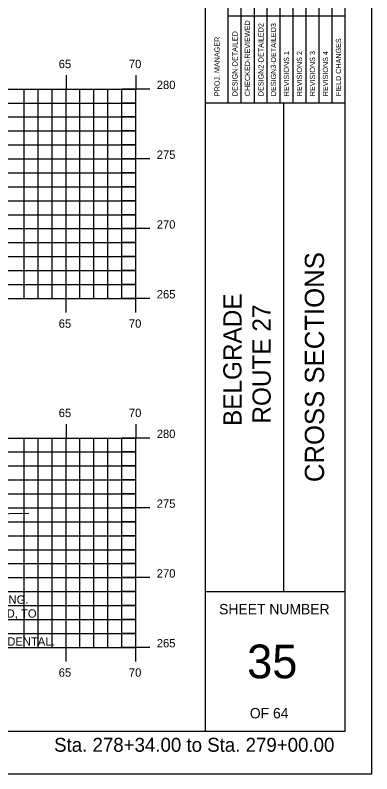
# Model space of a CAD drawing. Extents: x 854676 to 854846, y 366268 to 366378.
# Drawn here: x 854820.5 to 854846, y 366268.2 to 366322.5 of the extents above; entities that cross this region are included whole.
import ezdxf

# ---------------------------------------------------------------- set-up
doc = ezdxf.new("R2010")
doc.units = 0
for name, color, linetype in [('ANNOTATION', 7, 'Continuous'), ('BORDER', 7, 'Continuous'), ('H_V ANNOTATION', 7, 'Continuous'), ('HIGHWAY_TITLE', 7, 'Continuous'), ('MAJOR', 7, 'Continuous'), ('MINOR', 7, 'Continuous'), ('PLOT BOUNDARY', 7, 'Continuous'), ('S_Roadway_Centerline', 7, 'Continuous')]:
    doc.layers.add(name, color=color, linetype=linetype)

msp = doc.modelspace()

# ---------------------------------------------------------------- linework, layer by layer
at = {"layer": 'BORDER'}
for p, q in [((854834.107, 366271.236), (854834.107, 366376.239)), ((854844.107, 366271.236), (854844.107, 366376.236)), ((854834.107, 366316.239), (854844.107, 366316.239)), ((854839.698, 366281.239), (854839.698, 366316.239)), ((854834.107, 366281.239), (854844.107, 366281.239)), ((854684.107, 366271.236), (854844.107, 366271.236))]:
    msp.add_line(p, q, dxfattribs=at)
for points in [[(854836.654, 366316.242), (854836.654, 366333.739)], [(854837.586, 366333.739), (854837.586, 366316.242)], [(854838.517, 366316.242), (854838.517, 366333.739)], [(854839.449, 366316.242), (854839.449, 366333.739)], [(854840.381, 366316.242), (854840.381, 366333.739)], [(854841.312, 366316.242), (854841.312, 366333.739)], [(854842.244, 366316.242), (854842.244, 366333.739)], [(854843.176, 366316.242), (854843.176, 366333.739)], [(854835.722, 366316.242), (854835.722, 366333.033)], [(854835.721, 366322.489), (854844.107, 366322.489)]]:
    msp.add_lwpolyline(points, dxfattribs=at)
at = {"layer": 'MAJOR'}
for p, q in [((854824.106, 366318.238), (854824.106, 366317.236)), ((854829.106, 366318.238), (854829.106, 366317.236)), ((854689.106, 366317.236), (854829.106, 366317.236)), ((854689.106, 366317.236), (854829.106, 366317.236)), ((854824.106, 366302.236), (854824.106, 366317.236)), ((854830.108, 366317.236), (854828.104, 366317.236)), ((854829.106, 366302.236), (854829.106, 366317.236)), ((854829.106, 366302.236), (854829.106, 366317.236)), ((854689.106, 366312.236), (854829.106, 366312.236)), ((854830.108, 366312.236), (854828.104, 366312.236)), ((854689.106, 366307.236), (854829.106, 366307.236)), ((854830.108, 366307.236), (854828.104, 366307.236)), ((854689.106, 366302.236), (854829.106, 366302.236)), ((854689.106, 366302.236), (854829.106, 366302.236)), ((854824.106, 366301.234), (854824.106, 366302.236)), ((854830.108, 366302.236), (854828.104, 366302.236)), ((854829.106, 366301.234), (854829.106, 366302.236)), ((854824.106, 366293.238), (854824.106, 366292.236)), ((854829.106, 366293.238), (854829.106, 366292.236)), ((854689.106, 366292.236), (854829.106, 366292.236)), ((854689.106, 366292.236), (854829.106, 366292.236)), ((854824.106, 366277.236), (854824.106, 366292.236)), ((854830.108, 366292.236), (854828.104, 366292.236)), ((854829.106, 366277.236), (854829.106, 366292.236)), ((854829.106, 366277.236), (854829.106, 366292.236)), ((854689.106, 366287.236), (854829.106, 366287.236)), ((854830.108, 366287.236), (854828.104, 366287.236)), ((854689.106, 366282.236), (854829.106, 366282.236)), ((854830.108, 366282.236), (854828.104, 366282.236)), ((854689.106, 366277.236), (854829.106, 366277.236)), ((854689.106, 366277.236), (854829.106, 366277.236)), ((854824.106, 366276.234), (854824.106, 366277.236)), ((854830.108, 366277.236), (854828.104, 366277.236)), ((854829.106, 366276.234), (854829.106, 366277.236))]:
    msp.add_line(p, q, dxfattribs=at)
at = {"layer": 'MINOR'}
for p, q in [((854821.106, 366302.236), (854821.106, 366317.236)), ((854822.106, 366302.236), (854822.106, 366317.236)), ((854823.106, 366302.236), (854823.106, 366317.236)), ((854825.106, 366302.236), (854825.106, 366317.236)), ((854826.106, 366302.236), (854826.106, 366317.236)), ((854827.106, 366302.236), (854827.106, 366317.236)), ((854828.106, 366302.236), (854828.106, 366317.236)), ((854689.106, 366316.236), (854829.106, 366316.236)), ((854829.106, 366316.236), (854828.104, 366316.236)), ((854689.106, 366315.236), (854829.106, 366315.236)), ((854829.106, 366315.236), (854828.104, 366315.236)), ((854689.106, 366314.236), (854829.106, 366314.236)), ((854829.106, 366314.236), (854828.104, 366314.236)), ((854689.106, 366313.236), (854829.106, 366313.236)), ((854829.106, 366313.236), (854828.104, 366313.236)), ((854689.106, 366311.236), (854829.106, 366311.236)), ((854829.106, 366311.236), (854828.104, 366311.236)), ((854689.106, 366310.236), (854829.106, 366310.236)), ((854829.106, 366310.236), (854828.104, 366310.236)), ((854689.106, 366309.236), (854829.106, 366309.236)), ((854829.106, 366309.236), (854828.104, 366309.236)), ((854689.106, 366308.236), (854829.106, 366308.236)), ((854829.106, 366308.236), (854828.104, 366308.236)), ((854689.106, 366306.236), (854829.106, 366306.236)), ((854829.106, 366306.236), (854828.104, 366306.236)), ((854689.106, 366305.236), (854829.106, 366305.236)), ((854829.106, 366305.236), (854828.104, 366305.236)), ((854689.106, 366304.236), (854829.106, 366304.236)), ((854829.106, 366304.236), (854828.104, 366304.236)), ((854689.106, 366303.236), (854829.106, 366303.236)), ((854829.106, 366303.236), (854828.104, 366303.236)), ((854821.106, 366277.236), (854821.106, 366292.236)), ((854822.106, 366277.236), (854822.106, 366292.236)), ((854823.106, 366277.236), (854823.106, 366292.236)), ((854825.106, 366277.236), (854825.106, 366292.236)), ((854826.106, 366277.236), (854826.106, 366292.236)), ((854827.106, 366277.236), (854827.106, 366292.236)), ((854828.106, 366277.236), (854828.106, 366292.236)), ((854689.106, 366291.236), (854829.106, 366291.236)), ((854829.106, 366291.236), (854828.104, 366291.236)), ((854689.106, 366290.236), (854829.106, 366290.236)), ((854829.106, 366290.236), (854828.104, 366290.236)), ((854689.106, 366289.236), (854829.106, 366289.236)), ((854829.106, 366289.236), (854828.104, 366289.236)), ((854689.106, 366288.236), (854829.106, 366288.236)), ((854829.106, 366288.236), (854828.104, 366288.236)), ((854689.106, 366286.236), (854829.106, 366286.236)), ((854829.106, 366286.236), (854828.104, 366286.236)), ((854689.106, 366285.236), (854829.106, 366285.236)), ((854829.106, 366285.236), (854828.104, 366285.236)), ((854689.106, 366284.236), (854829.106, 366284.236)), ((854829.106, 366284.236), (854828.104, 366284.236)), ((854689.106, 366283.236), (854829.106, 366283.236)), ((854829.106, 366283.236), (854828.104, 366283.236)), ((854689.106, 366281.236), (854829.106, 366281.236)), ((854829.106, 366281.236), (854828.104, 366281.236)), ((854689.106, 366280.236), (854829.106, 366280.236)), ((854829.106, 366280.236), (854828.104, 366280.236)), ((854689.106, 366279.236), (854829.106, 366279.236)), ((854829.106, 366279.236), (854828.104, 366279.236)), ((854689.106, 366278.236), (854829.106, 366278.236)), ((854829.106, 366278.236), (854828.104, 366278.236))]:
    msp.add_line(p, q, dxfattribs=at)
at = {"layer": 'PLOT BOUNDARY'}
msp.add_lwpolyline([(854676.013, 366268.177), (854846.013, 366268.177), (854846.013, 366378.177), (854676.013, 366378.177)], close=True, dxfattribs=at)
at = {"layer": 'S_Roadway_Centerline'}
msp.add_lwpolyline([(854761.239, 366285.468), (854771.879, 366285.217), (854773.739, 366285.161), (854773.78, 366285.165), (854779.318, 366284.958), (854780.092, 366285.127), (854781.22, 366285.244), (854783.057, 366285.522), (854785.139, 366285.725), (854788.523, 366286.018), (854794.872, 366286.31), (854809.217, 366286.68), (854809.259, 366286.671), (854815.82, 366286.767), (854821.433, 366286.854)], dxfattribs=at)

# ---------------------------------------------------------------- texts
at = {"layer": 'ANNOTATION'}
for s, p in [('REMOVE AND RESET LANDSCAPE TIMBER EDGING.', (854801.173, 366280.361)), ('BEVEL END OF LANDSCAPE TIMBER, AS NEEDED, TO', (854801.173, 366279.361)), ('TO LANDSCAPE TIMBER EDGING SHALL BE INCIDENTAL.', (854801.173, 366277.361))]:
    msp.add_text(s, height=0.6, dxfattribs=at).set_placement(p)
at = {"layer": 'BORDER'}
for s, height, rotation, p in [('CHECKED-REVIEWED', 0.37275, 90, (854837.288, 366316.727)), ('DESIGN2-DETAILED2', 0.37275, 90, (854838.256, 366316.727)), ('DESIGN3-DETAILED3', 0.37275, 90, (854839.151, 366316.727)), ('DESIGN-DETAILED', 0.37275, 90, (854836.393, 366316.727)), ('PROJ. MANAGER', 0.37275, 90, (854835.111, 366316.727)), ('FIELD CHANGES', 0.37275, 90, (854843.809, 366316.727)), ('REVISIONS 1', 0.37275, 90, (854840.083, 366316.727)), ('REVISIONS 2', 0.37275, 90, (854841.014, 366316.727)), ('REVISIONS 3', 0.37275, 90, (854841.946, 366316.727)), ('REVISIONS 4', 0.37275, 90, (854842.878, 366316.727)), ('CROSS SECTIONS', 1.37787, 90, (854842.591, 366289.073)), ('SHEET NUMBER', 0.74527, 360, (854835.072, 366279.603)), ('35', 2.4194, 360, (854837.082, 366275.019)), ('OF 64', 0.7453, 360, (854837.273, 366272.149))]:
    msp.add_text(s, height=height, rotation=rotation, dxfattribs=at).set_placement(p)
at = {"layer": 'H_V ANNOTATION'}
for s, height, p in [('65', 0.6, (854823.584, 366318.736)), ('70', 0.6, (854828.608, 366318.736)), ('280', 0.6, (854830.606, 366317.236)), ('275', 0.6, (854830.606, 366312.236)), ('270', 0.6, (854830.606, 366307.236)), ('265', 0.6, (854830.606, 366302.236)), ('65', 0.6, (854823.584, 366300.136)), ('70', 0.6, (854828.608, 366300.136)), ('65', 0.6, (854823.584, 366293.736)), ('70', 0.6, (854828.608, 366293.736)), ('280', 0.6, (854830.606, 366292.236)), ('275', 0.6, (854830.606, 366287.236)), ('270', 0.6, (854830.606, 366282.236)), ('265', 0.6, (854830.606, 366277.236)), ('65', 0.6, (854823.584, 366275.136)), ('70', 0.6, (854828.608, 366275.136)), ('Sta. 278+34.00 to Sta. 279+00.00', 1.0002, (854823.252, 366269.756))]:
    msp.add_text(s, height=height, dxfattribs=at).set_placement(p)
at = {"layer": 'HIGHWAY_TITLE'}
for s, p in [('BELGRADE', (854836.679, 366293.095)), ('ROUTE 27', (854838.766, 366293.269))]:
    msp.add_text(s, height=1.3043, rotation=90, dxfattribs=at).set_placement(p)

doc.saveas('drawing.dxf')
